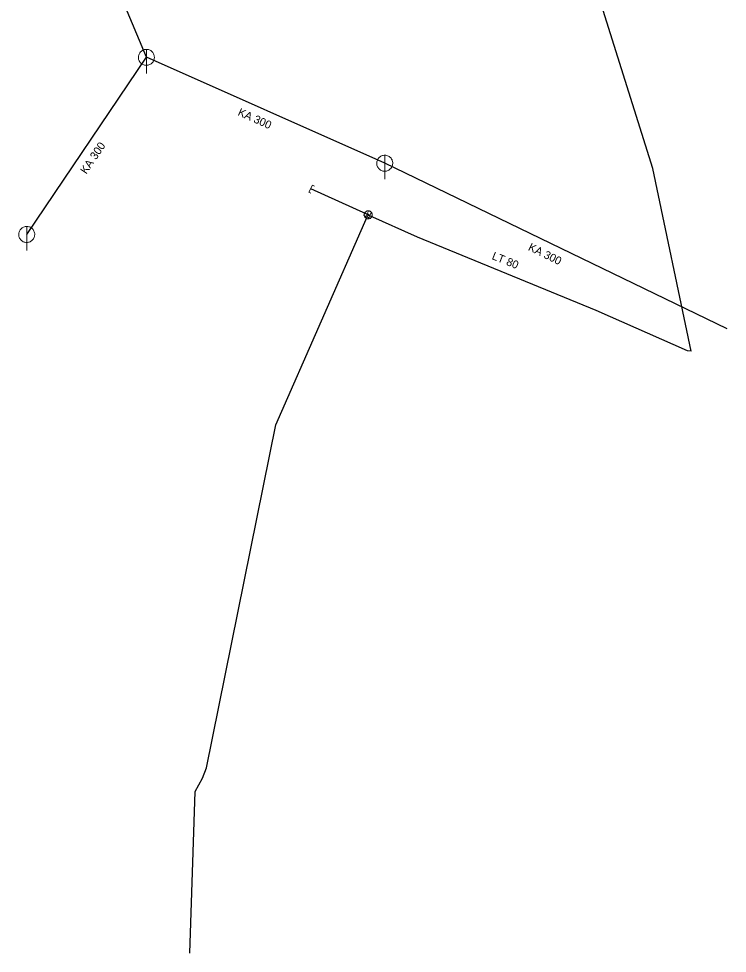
# Model space of a CAD drawing. Extents: x -690535 to -689974, y -975624 to -975325.
# Drawn here: x -690183.9 to -690095.4, y -975589 to -975472.2 of the extents above; entities that cross this region are included whole.
import ezdxf

# ---------------------------------------------------------------- set-up
doc = ezdxf.new("R2010")
doc.units = 0
doc.header["$LTSCALE"] = 0.4
for name, color, linetype, lineweight in [('1', 7, 'Continuous', 13), ('14', 7, 'Continuous', 25), ('17', 7, 'Continuous', 25), ('22', 7, 'Continuous', 13), ('34', 7, 'Continuous', 13), ('47', 7, 'Continuous', 13)]:
    doc.layers.add(name, color=color, linetype=linetype, lineweight=lineweight)

msp = doc.modelspace()

# ---------------------------------------------------------------- linework, layer by layer
at = {"layer": '14'}
for p, q in [((-690138.198, -975490.268), (-690167.964, -975477.038)), ((-690095.425, -975510.964), (-690138.198, -975490.268))]:
    msp.add_line(p, q, dxfattribs=at)
at = {"layer": '14', "lineweight": 13}
msp.add_line((-690140.261, -975496.715), (-690140.418, -975496.64), dxfattribs=at)
at = {"layer": '14'}
msp.add_lwpolyline([(-690182.905, -975499.167), (-690167.964, -975477.038), (-690178.021, -975453.002)], dxfattribs=at)
at = {"layer": '14', "lineweight": 13}
msp.add_lwpolyline([(-690140.378, -975496.971), (-690140.261, -975496.715), (-690140.074, -975496.826)], dxfattribs=at)
at = {"layer": '17'}
msp.add_line((-690140.418, -975496.64), (-690147.432, -975493.451), dxfattribs=at)
for points in [[(-690099.953, -975513.738), (-690104.725, -975490.907), (-690130.226, -975409.671)], [(-690162.524, -975588.984), (-690161.853, -975568.787), (-690160.953, -975567.113), (-690160.438, -975565.826), (-690151.817, -975522.965), (-690140.378, -975496.971)], [(-690099.953, -975513.738), (-690100.388, -975513.698), (-690111.816, -975508.677), (-690134.118, -975499.502), (-690140.074, -975496.826)]]:
    msp.add_lwpolyline(points, dxfattribs=at)
at = {"layer": '22'}
for p, q in [((-690167.964, -975479.038), (-690167.963, -975476.038)), ((-690138.198, -975492.268), (-690138.197, -975489.268)), ((-690182.905, -975501.167), (-690182.904, -975498.167))]:
    msp.add_line(p, q, dxfattribs=at)
for points in [[(-690166.964, -975477.038), (-690166.969, -975476.929), (-690166.987, -975476.821), (-690167.017, -975476.715), (-690167.057, -975476.614), (-690167.109, -975476.517), (-690167.171, -975476.427), (-690167.243, -975476.344), (-690167.323, -975476.27), (-690167.411, -975476.204), (-690167.505, -975476.149), (-690167.605, -975476.104), (-690167.71, -975476.071), (-690167.817, -975476.049), (-690167.926, -975476.039), (-690168.036, -975476.041), (-690168.144, -975476.055), (-690168.251, -975476.08), (-690168.354, -975476.117), (-690168.452, -975476.166), (-690168.544, -975476.224), (-690168.63, -975476.293), (-690168.707, -975476.37), (-690168.776, -975476.456), (-690168.835, -975476.548), (-690168.883, -975476.646), (-690168.92, -975476.749), (-690168.946, -975476.856), (-690168.96, -975476.964), (-690168.963, -975477.074), (-690168.953, -975477.183), (-690168.932, -975477.29), (-690168.898, -975477.394), (-690168.854, -975477.494), (-690168.799, -975477.589), (-690168.733, -975477.677), (-690168.659, -975477.757), (-690168.576, -975477.829), (-690168.486, -975477.891), (-690168.39, -975477.943), (-690168.288, -975477.984), (-690168.183, -975478.014), (-690168.075, -975478.032), (-690167.965, -975478.038), (-690167.856, -975478.032), (-690167.748, -975478.014), (-690167.643, -975477.985), (-690167.541, -975477.944), (-690167.444, -975477.892), (-690167.354, -975477.83), (-690167.271, -975477.759), (-690167.196, -975477.679), (-690167.131, -975477.591), (-690167.075, -975477.497), (-690167.031, -975477.397), (-690166.997, -975477.293), (-690166.975, -975477.185), (-690166.965, -975477.076)], [(-690137.198, -975490.268), (-690137.203, -975490.159), (-690137.221, -975490.051), (-690137.251, -975489.945), (-690137.291, -975489.844), (-690137.343, -975489.747), (-690137.405, -975489.657), (-690137.477, -975489.574), (-690137.557, -975489.5), (-690137.645, -975489.434), (-690137.739, -975489.379), (-690137.839, -975489.334), (-690137.944, -975489.301), (-690138.051, -975489.279), (-690138.16, -975489.269), (-690138.27, -975489.271), (-690138.378, -975489.285), (-690138.485, -975489.31), (-690138.588, -975489.347), (-690138.686, -975489.396), (-690138.778, -975489.454), (-690138.864, -975489.523), (-690138.941, -975489.6), (-690139.01, -975489.686), (-690139.069, -975489.778), (-690139.117, -975489.876), (-690139.154, -975489.979), (-690139.18, -975490.086), (-690139.194, -975490.194), (-690139.197, -975490.304), (-690139.187, -975490.413), (-690139.166, -975490.52), (-690139.132, -975490.624), (-690139.088, -975490.724), (-690139.033, -975490.819), (-690138.967, -975490.907), (-690138.893, -975490.987), (-690138.81, -975491.059), (-690138.72, -975491.121), (-690138.624, -975491.173), (-690138.522, -975491.214), (-690138.417, -975491.244), (-690138.309, -975491.262), (-690138.199, -975491.268), (-690138.09, -975491.262), (-690137.982, -975491.244), (-690137.877, -975491.215), (-690137.775, -975491.174), (-690137.678, -975491.122), (-690137.588, -975491.06), (-690137.505, -975490.989), (-690137.43, -975490.909), (-690137.365, -975490.821), (-690137.309, -975490.727), (-690137.265, -975490.627), (-690137.231, -975490.523), (-690137.209, -975490.415), (-690137.199, -975490.306)], [(-690181.905, -975499.167), (-690181.91, -975499.058), (-690181.928, -975498.95), (-690181.958, -975498.844), (-690181.998, -975498.743), (-690182.05, -975498.646), (-690182.112, -975498.556), (-690182.184, -975498.473), (-690182.264, -975498.399), (-690182.352, -975498.333), (-690182.446, -975498.278), (-690182.546, -975498.233), (-690182.651, -975498.2), (-690182.758, -975498.178), (-690182.867, -975498.168), (-690182.977, -975498.17), (-690183.085, -975498.184), (-690183.192, -975498.209), (-690183.295, -975498.246), (-690183.393, -975498.295), (-690183.485, -975498.353), (-690183.571, -975498.422), (-690183.648, -975498.499), (-690183.717, -975498.585), (-690183.776, -975498.677), (-690183.824, -975498.775), (-690183.861, -975498.878), (-690183.887, -975498.985), (-690183.901, -975499.093), (-690183.904, -975499.203), (-690183.894, -975499.312), (-690183.873, -975499.419), (-690183.839, -975499.523), (-690183.795, -975499.623), (-690183.74, -975499.718), (-690183.674, -975499.806), (-690183.6, -975499.886), (-690183.517, -975499.958), (-690183.427, -975500.02), (-690183.331, -975500.072), (-690183.229, -975500.113), (-690183.124, -975500.143), (-690183.016, -975500.161), (-690182.906, -975500.167), (-690182.797, -975500.161), (-690182.689, -975500.143), (-690182.584, -975500.114), (-690182.482, -975500.073), (-690182.385, -975500.021), (-690182.295, -975499.959), (-690182.212, -975499.888), (-690182.137, -975499.808), (-690182.072, -975499.72), (-690182.016, -975499.626), (-690181.972, -975499.526), (-690181.938, -975499.422), (-690181.916, -975499.314), (-690181.906, -975499.205)]]:
    msp.add_lwpolyline(points, close=True, dxfattribs=at)
at = {"layer": '34'}
for p, q in [((-690140.191, -975496.194), (-690140.645, -975497.085)), ((-690140.835, -975496.77), (-690139.92, -975497.172)), ((-690139.849, -975496.379), (-690140.299, -975497.272))]:
    msp.add_line(p, q, dxfattribs=at)
at = {"layer": '47'}
msp.add_lwpolyline([(-690147.432, -975494.007), (-690147.657, -975493.892), (-690147.206, -975493.009), (-690146.982, -975493.123)], dxfattribs=at)
for points in [[(-690139.814, -975496.939), (-690139.793, -975496.892), (-690139.777, -975496.841), (-690139.767, -975496.791), (-690139.761, -975496.739), (-690139.761, -975496.686), (-690139.767, -975496.634), (-690139.779, -975496.583), (-690139.795, -975496.533), (-690139.816, -975496.486), (-690139.843, -975496.44), (-690139.874, -975496.398), (-690139.909, -975496.359), (-690139.948, -975496.324), (-690139.991, -975496.294), (-690140.036, -975496.268), (-690140.083, -975496.247), (-690140.134, -975496.231), (-690140.185, -975496.221), (-690140.236, -975496.215), (-690140.289, -975496.215), (-690140.341, -975496.221), (-690140.393, -975496.232), (-690140.443, -975496.249), (-690140.49, -975496.27), (-690140.535, -975496.297), (-690140.577, -975496.328), (-690140.616, -975496.363), (-690140.651, -975496.402), (-690140.681, -975496.445), (-690140.707, -975496.49), (-690140.728, -975496.537), (-690140.744, -975496.588), (-690140.755, -975496.639), (-690140.76, -975496.69), (-690140.76, -975496.743), (-690140.754, -975496.795), (-690140.743, -975496.846), (-690140.727, -975496.896), (-690140.705, -975496.944), (-690140.678, -975496.989), (-690140.647, -975497.031), (-690140.613, -975497.07), (-690140.573, -975497.105), (-690140.53, -975497.135), (-690140.485, -975497.161), (-690140.438, -975497.182), (-690140.387, -975497.198), (-690140.337, -975497.209), (-690140.285, -975497.214), (-690140.232, -975497.214), (-690140.18, -975497.208), (-690140.129, -975497.197), (-690140.08, -975497.181), (-690140.032, -975497.159), (-690139.986, -975497.132), (-690139.944, -975497.101), (-690139.906, -975497.067), (-690139.87, -975497.027), (-690139.84, -975496.984)], [(-690140.187, -975496.751), (-690140.183, -975496.743), (-690140.181, -975496.735), (-690140.18, -975496.727), (-690140.179, -975496.719), (-690140.179, -975496.71), (-690140.18, -975496.701), (-690140.181, -975496.693), (-690140.184, -975496.685), (-690140.188, -975496.677), (-690140.192, -975496.67), (-690140.197, -975496.662), (-690140.203, -975496.656), (-690140.209, -975496.651), (-690140.216, -975496.645), (-690140.224, -975496.641), (-690140.232, -975496.637), (-690140.24, -975496.635), (-690140.248, -975496.634), (-690140.256, -975496.633), (-690140.265, -975496.633), (-690140.274, -975496.634), (-690140.282, -975496.635), (-690140.29, -975496.638), (-690140.299, -975496.641), (-690140.305, -975496.646), (-690140.313, -975496.651), (-690140.319, -975496.657), (-690140.324, -975496.663), (-690140.33, -975496.67), (-690140.334, -975496.678), (-690140.338, -975496.686), (-690140.34, -975496.694), (-690140.341, -975496.702), (-690140.342, -975496.71), (-690140.342, -975496.719), (-690140.342, -975496.727), (-690140.34, -975496.736), (-690140.337, -975496.744), (-690140.334, -975496.753), (-690140.329, -975496.759), (-690140.324, -975496.767), (-690140.318, -975496.773), (-690140.312, -975496.778), (-690140.305, -975496.784), (-690140.297, -975496.788), (-690140.289, -975496.792), (-690140.281, -975496.794), (-690140.273, -975496.795), (-690140.265, -975496.796), (-690140.256, -975496.796), (-690140.248, -975496.796), (-690140.239, -975496.794), (-690140.231, -975496.791), (-690140.223, -975496.787), (-690140.216, -975496.783), (-690140.208, -975496.778), (-690140.202, -975496.772), (-690140.197, -975496.766), (-690140.191, -975496.759)]]:
    msp.add_lwpolyline(points, close=True, dxfattribs=at)

# ---------------------------------------------------------------- texts
at = {"layer": '1'}
for s, rotation, p in [('KA 300', 336, (-690156.628, -975484.248)), ('KA 300', 56, (-690175.467, -975491.699)), ('KA 300', 334, (-690120.376, -975501.096)), ('LT 80 ', 338, (-690124.904, -975502.227))]:
    msp.add_text(s, height=1, rotation=rotation, dxfattribs=at).set_placement(p)

doc.saveas('drawing.dxf')
